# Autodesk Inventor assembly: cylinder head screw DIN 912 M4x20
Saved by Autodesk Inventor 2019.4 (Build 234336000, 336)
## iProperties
Created: 2021-08
Part Number: cylinder head screw DIN 912 M4x20
Document SubType Name: Assembly
Designer: Administrator
Title: cylinder head screw DIN 912 M4x20 v4
Author: Administrator
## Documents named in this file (2)
- c:\worker\convert-fusion-r06\tmp\job-1\20\output\files\f01db8e3-9ba6-469c-91a4-18b8ab1b818d\cylinder head screw DIN 912 M4x20 v4_3.iam
- c:\worker\convert-fusion-r06\tmp\job-1\20\output\files\f01db8e3-9ba6-469c-91a4-18b8ab1b818d\HI_WUERTH 00824  20 cylinder head screw DIN 912 M4x20 8.8 BLK.ipt
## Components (1 placed, 1 different names)
1. HI_WUERTH 00824  20 cylinder head screw DIN 912 M4x20 8.8 BLK:1
